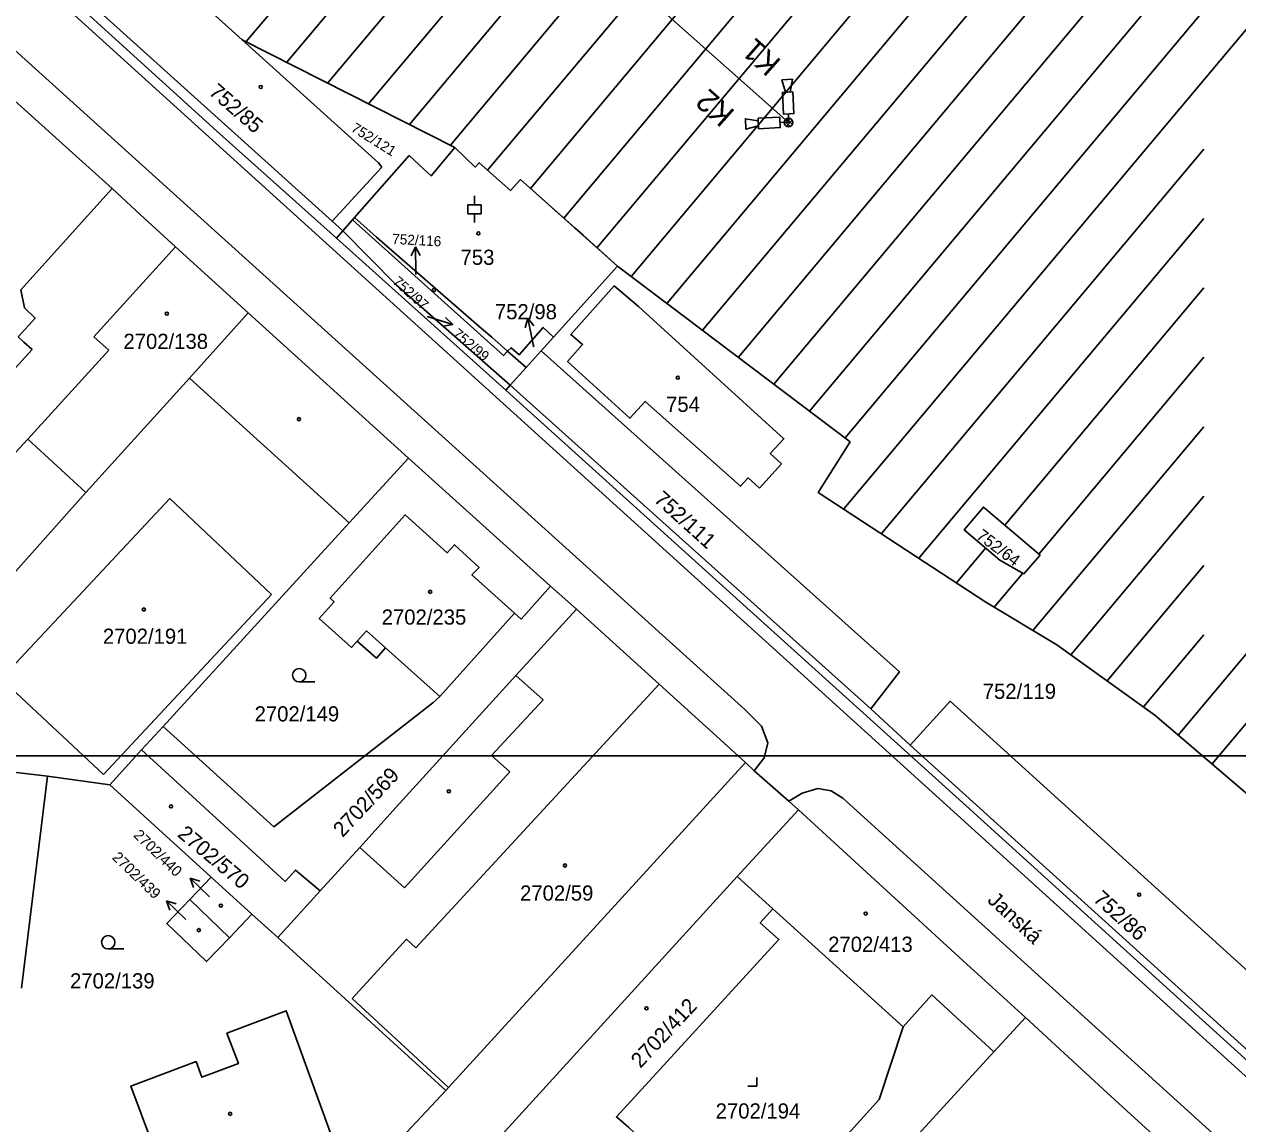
# Model space of a CAD drawing. Extents: x -496682 to -495776, y -1088797 to -1088018.
# Drawn here: x -496329.9 to -496193.9, y -1088502.5 to -1088379.3 of the extents above; entities that cross this region are included whole.
import ezdxf

# ---------------------------------------------------------------- set-up
doc = ezdxf.new("R2010")
doc.units = 0
for name, color, linetype in [('_PS01_CCTV', 7, 'Continuous'), ('Default', 7, 'Continuous'), ('Hranice parcel', 7, 'Continuous'), ('Parcelní čísla', 7, 'Continuous'), ('Pop  PČ popisy', 7, 'Continuous'), ('Vnitřní kresba', 7, 'Continuous'), ('Vrstva 20', 7, 'Continuous'), ('Vrstva 54', 7, 'Continuous'), ('Vrstva 63', 7, 'Continuous'), ('Značky budov', 7, 'Continuous'), ('Značky kultur', 7, 'Continuous')]:
    doc.layers.add(name, color=color, linetype=linetype)

# ---------------------------------------------------------------- blocks, each defined once
blk = doc.blocks.new('kamera na stožáru')
at = {"layer": 'Default'}
for p, q in [((-0.00047, -0.00014), (0.00014, 0.00046)), ((-0.00024, -0.00043), (0.00043, 0.00023)), ((0.00005, 0.00096), (0.00003, 0))]:
    blk.add_line(p, q, dxfattribs=at)
blk.add_lwpolyline([(0.00036, 0.00339), (0.00066, 0.00481), (-0.00052, 0.00481), (-0.00019, 0.0034)], dxfattribs=at)
blk.add_lwpolyline([(0.00065, 0.00339), (0.00064, 0.00096), (-0.00053, 0.00096), (-0.00053, 0.0034)], close=True, dxfattribs=at)
blk.add_circle((0, 0), 0.000488, dxfattribs=at)
blk.add_circle((0, 0), 0.000488, dxfattribs=at)
blk.add_circle((0, 0), 0.000488, dxfattribs=at)

msp = doc.modelspace()

# ---------------------------------------------------------------- linework, layer by layer
at = {"layer": '_PS01_CCTV'}
msp.add_line((-496244.22, -1088390.26), (-496278.91, -1088359.52), dxfattribs=at)
at = {"layer": 'Hranice parcel'}
for p, q in [((-496295.37, -1088401.32), (-496330.83, -1088369.38)), ((-496305.46, -1088381.01), (-496281.64, -1088393.07)), ((-496294.19, -1088402.41), (-496295.37, -1088401.32)), ((-496293.12, -1088401.19), (-496294.19, -1088402.41)), ((-496292.87, -1088400.91), (-496293.12, -1088401.19)), ((-496294.19, -1088402.41), (-496294.91, -1088403.24)), ((-496275.92, -1088420.27), (-496294.91, -1088403.24)), ((-496270.58, -1088414.34), (-496263.38, -1088406.35)), ((-496286.81, -1088427.89), (-496304.81, -1088411.58)), ((-496271.94, -1088415.85), (-496270.58, -1088414.34)), ((-496273.63, -1088417.73), (-496275.71, -1088415.91)), ((-496273.63, -1088417.73), (-496271.94, -1088415.85)), ((-496275.42, -1088419.72), (-496273.63, -1088417.73)), ((-496275.92, -1088420.27), (-496275.42, -1088419.72)), ((-496235.01, -1088455.98), (-496275.42, -1088419.72)), ((-496329.51, -1088425.77), (-496322.98, -1088431.74)), ((-496270.9, -1088442.22), (-496286.81, -1088427.89)), ((-496322.98, -1088431.74), (-496349.17, -1088461.01)), ((-496270.9, -1088442.22), (-496268.01, -1088444.81)), ((-496283.32, -1088454.6), (-496274.93, -1088445.27)), ((-496230.6, -1088460.05), (-496235.01, -1088455.98)), ((-496316.74, -1088460.58), (-496314.33, -1088457.95)), ((-496349.17, -1088461.01), (-496327.31, -1088463.52)), ((-496320.32, -1088464.49), (-496316.74, -1088460.58)), ((-496185.86, -1088500.52), (-496230.6, -1088460.05)), ((-496248.09, -1088462.93), (-496249.03, -1088461.98)), ((-496327.31, -1088463.52), (-496330.22, -1088487.27)), ((-496320.32, -1088464.49), (-496327.31, -1088463.52)), ((-496244.2, -1088466.33), (-496248.09, -1088462.93)), ((-496308.94, -1088474.84), (-496320.32, -1088464.49)), ((-496243.12, -1088467.31), (-496244.2, -1088466.33)), ((-496249.99, -1088474.77), (-496243.12, -1088467.31)), ((-496311.35, -1088477.35), (-496308.94, -1088474.84)), ((-496304.39, -1088478.97), (-496308.94, -1088474.84)), ((-496277.9, -1088505.38), (-496249.99, -1088474.77)), ((-496245.99, -1088478.39), (-496249.99, -1088474.77)), ((-496306.88, -1088481.63), (-496311.35, -1088477.35)), ((-496296.73, -1088476.39), (-496301.48, -1088481.61)), ((-496231.37, -1088491.6), (-496245.99, -1088478.39)), ((-496304.39, -1088478.97), (-496306.88, -1088481.63)), ((-496301.48, -1088481.61), (-496304.39, -1088478.97)), ((-496301.48, -1088481.61), (-496282.64, -1088498.73)), ((-496221.19, -1088494.41), (-496217.64, -1088490.55))]:
    msp.add_line(p, q, dxfattribs=at)
for points in [[(-496248.09, -1088462.93), (-496246.94, -1088461.48), (-496246.55, -1088459.79), (-496247.27, -1088457.92), (-496249.13, -1088456.06), (-496330.94, -1088382.16), (-496352.76, -1088362.17), (-496394.53, -1088322.76)], [(-496294.91, -1088403.24), (-496308.3, -1088391.23), (-496341.24, -1088361.35)], [(-496113.2, -1088569.45), (-496126.78, -1088557.15), (-496235.31, -1088458.83), (-496335.43, -1088368.13), (-496341.24, -1088361.35)], [(-496329.48, -1088364.15), (-496318.71, -1088373.85), (-496316.3, -1088371.21), (-496305.46, -1088381.01)], [(-496320.05, -1088397.68), (-496324.85, -1088393.33), (-496347.42, -1088372.97)], [(-496295.37, -1088401.32), (-496289.83, -1088395.26), (-496290.2, -1088394.8), (-496305.46, -1088381.01)], [(-496281.64, -1088393.07), (-496284.3, -1088396.25), (-496284.64, -1088395.96), (-496286.75, -1088393.98), (-496292.87, -1088400.91)], [(-496281.64, -1088393.07), (-496279.37, -1088395.26), (-496278.92, -1088394.77), (-496275.4, -1088397.89), (-496274.28, -1088396.67), (-496268.16, -1088402.12), (-496267.26, -1088402.88), (-496263.38, -1088406.35)], [(-496353.62, -1088434.72), (-496347.79, -1088428.16), (-496343.74, -1088431.85), (-496329.03, -1088415.71), (-496329.94, -1088414.89), (-496330.57, -1088414.27), (-496328.66, -1088412.18), (-496329.87, -1088411.04), (-496330.29, -1088409.02), (-496320.05, -1088397.68)], [(-496320.05, -1088397.68), (-496316.9, -1088400.57), (-496312.96, -1088404.2), (-496304.81, -1088411.58)], [(-496275.71, -1088415.91), (-496276.17, -1088416.39), (-496293.12, -1088401.19)], [(-496292.87, -1088400.91), (-496290.41, -1088403.13), (-496278.64, -1088413.37), (-496277.5, -1088414.34), (-496275.71, -1088415.91)], [(-496294.19, -1088402.41), (-496288.2, -1088408.47), (-496275.42, -1088419.72)], [(-496263.38, -1088406.35), (-496237.32, -1088426.06), (-496240.89, -1088431.73), (-496222.1, -1088444.04), (-496214.16, -1088448.81), (-496203.17, -1088456.69), (-496183.01, -1088473.86)], [(-496247.48, -1088431.25), (-496245.02, -1088428.51), (-496246.28, -1088427.38), (-496244.75, -1088425.7), (-496261.03, -1088410.9), (-496263.76, -1088408.58), (-496268.63, -1088414.01), (-496267.32, -1088415.15), (-496268.99, -1088417.07), (-496262.01, -1088423.42), (-496260.29, -1088421.52), (-496249.6, -1088431.03), (-496248.76, -1088430.1), (-496247.48, -1088431.25)], [(-496304.81, -1088411.58), (-496311.39, -1088418.91), (-496322.98, -1088431.74)], [(-496275.71, -1088415.91), (-496275.33, -1088415.51), (-496274.41, -1088416.29), (-496271.73, -1088413.23), (-496270.58, -1088414.34)], [(-496235.01, -1088455.98), (-496231.8, -1088451.84), (-496271.94, -1088415.85)], [(-496111.32, -1088569.45), (-496125.77, -1088556.38), (-496187.85, -1088499.89), (-496224.3, -1088466.84), (-496274.7, -1088421.37), (-496275.92, -1088420.27)], [(-496353.62, -1088434.72), (-496344.49, -1088436.33), (-496341.48, -1088433.73), (-496338.95, -1088435.92), (-496329.51, -1088425.77)], [(-496286.81, -1088427.89), (-496293.46, -1088435.15), (-496314.33, -1088457.95)], [(-496216.02, -1088438.77), (-496217.83, -1088440.84), (-496220.52, -1088439.31), (-496224.52, -1088435.92), (-496222.37, -1088433.36), (-496216.02, -1088438.77)], [(-496283.32, -1088454.6), (-496289.39, -1088449.15), (-496290.42, -1088450.31), (-496292.57, -1088448.38), (-496293.21, -1088449.09), (-496296.84, -1088445.84), (-496295.16, -1088443.98), (-496295.61, -1088443.57), (-496287.2, -1088434.24), (-496282.48, -1088438.48), (-496281.67, -1088437.59), (-496278.91, -1088440.14), (-496279.72, -1088440.96), (-496274.93, -1088445.27)], [(-496274.93, -1088445.27), (-496274.21, -1088445.91), (-496270.9, -1088442.22)], [(-496268.01, -1088444.81), (-496274.79, -1088452.23), (-496288.2, -1088467.01), (-496292.3, -1088471.51), (-496296.73, -1088476.39)], [(-496249.03, -1088461.98), (-496258.73, -1088453.21), (-496268.01, -1088444.81)], [(-496314.33, -1088457.95), (-496301.91, -1088469.21), (-496284.09, -1088455.32), (-496283.32, -1088454.6)], [(-496185.86, -1088500.52), (-496181.41, -1088495.65), (-496226.11, -1088455.1), (-496230.6, -1088460.05)], [(-496316.74, -1088460.58), (-496305.3, -1088471.05), (-496300.65, -1088475.31), (-496299.49, -1088474.04), (-496296.73, -1088476.39)], [(-496282.64, -1088498.73), (-496282.35, -1088498.41), (-496249.03, -1088461.98)], [(-496244.2, -1088466.33), (-496242.71, -1088465.41), (-496240.93, -1088464.91), (-496239.45, -1088465.16), (-496238.15, -1088465.99), (-496132.08, -1088562.07), (-496131.43, -1088562.99), (-496131.42, -1088564), (-496132.07, -1088565.26)], [(-496217.64, -1088490.55), (-496224.63, -1088484.22), (-496243.12, -1088467.31)], [(-496306.88, -1088481.63), (-496309.46, -1088484.31), (-496313.92, -1088480.03), (-496311.35, -1088477.35)], [(-496245.99, -1088478.39), (-496247.4, -1088479.95), (-496245.31, -1088481.83), (-496263.51, -1088501.71), (-496262.11, -1088502.91), (-496260.17, -1088504.72), (-496261.08, -1088505.74), (-496268.24, -1088513.68)], [(-496231.37, -1088491.6), (-496228.16, -1088488.03), (-496221.19, -1088494.41)], [(-496305.69, -1088507.24), (-496310.68, -1088509.11), (-496311.29, -1088507.46), (-496313.75, -1088508.38), (-496313.97, -1088507.79), (-496315.1, -1088504.6), (-496315.52, -1088504.76), (-496317.97, -1088498.28), (-496310.64, -1088495.51), (-496309.98, -1088497.27), (-496305.9, -1088495.73), (-496307.18, -1088492.33), (-496300.54, -1088489.82), (-496295.6, -1088503.41), (-496302.16, -1088505.89)], [(-496190.39, -1088515.55), (-496208.5, -1088499), (-496217.64, -1088490.55)], [(-496268.24, -1088513.68), (-496265.8, -1088515.77), (-496265.43, -1088515.37), (-496255.1, -1088526.07), (-496251.45, -1088521.81), (-496251.15, -1088518.66), (-496234.05, -1088499.76), (-496231.37, -1088491.6)], [(-496221.19, -1088494.41), (-496230.49, -1088504.55), (-496214.35, -1088519.32)], [(-496282.64, -1088498.73), (-496287, -1088503.42), (-496289.92, -1088506.42), (-496292.31, -1088508.31), (-496294.86, -1088509.98), (-496297.59, -1088511.42), (-496300.41, -1088512.61), (-496303.13, -1088513.62), (-496305.98, -1088514.4), (-496309.41, -1088514.94), (-496310.93, -1088514.97), (-496313.55, -1088515.26), (-496317.24, -1088515.06), (-496320.12, -1088514.76), (-496333.4, -1088513.15)]]:
    msp.add_lwpolyline(points, dxfattribs=at)
at = {"layer": 'Pop  PČ popisy'}
for p, q in [((-496286.05, -1088404.19), (-496286.54, -1088405.2)), ((-496286, -1088407.19), (-496286.05, -1088404.19)), ((-496286.05, -1088404.19), (-496285.53, -1088405.18)), ((-496285.99, -1088407.3), (-496286, -1088407.19)), ((-496284.72, -1088412.02), (-496281.85, -1088412.9)), ((-496281.85, -1088412.9), (-496282.66, -1088412.13)), ((-496273.46, -1088412.2), (-496273.75, -1088413.28)), ((-496272.84, -1088415.13), (-496273.46, -1088412.2)), ((-496273.46, -1088412.2), (-496272.77, -1088413.07)), ((-496281.85, -1088412.9), (-496282.95, -1088413.08)), ((-496272.78, -1088415.41), (-496272.84, -1088415.13)), ((-496309.14, -1088477.04), (-496311.3, -1088474.96)), ((-496311.3, -1088474.96), (-496310.23, -1088475.29)), ((-496311.3, -1088474.96), (-496310.93, -1088476.01)), ((-496311.79, -1088479.58), (-496313.95, -1088477.5)), ((-496313.95, -1088477.5), (-496312.88, -1088477.83)), ((-496313.95, -1088477.5), (-496313.58, -1088478.55))]:
    msp.add_line(p, q, dxfattribs=at)
at = {"layer": 'Vnitřní kresba'}
for p, q in [((-496312.96, -1088404.2), (-496322.1, -1088414.27)), ((-496322.1, -1088414.27), (-496320.41, -1088415.8)), ((-496320.41, -1088415.8), (-496329.51, -1088425.77)), ((-496293.46, -1088435.15), (-496311.39, -1088418.91)), ((-496332.48, -1088452.62), (-496313.58, -1088432.42)), ((-496313.58, -1088432.42), (-496302.2, -1088443.15)), ((-496302.2, -1088443.15), (-496321.03, -1088463.34)), ((-496291.53, -1088447.22), (-496292.57, -1088448.38)), ((-496289.39, -1088449.15), (-496291.53, -1088447.22)), ((-496321.03, -1088463.34), (-496332.48, -1088452.62)), ((-496271.73, -1088454.95), (-496274.79, -1088452.23)), ((-496285.99, -1088482.77), (-496258.73, -1088453.21)), ((-496277.51, -1088461.21), (-496271.73, -1088454.95)), ((-496275.48, -1088463.04), (-496277.51, -1088461.21)), ((-496287.29, -1088476.05), (-496275.48, -1088463.04)), ((-496292.3, -1088471.51), (-496287.29, -1088476.05)), ((-496293.16, -1088488.43), (-496287.06, -1088481.79)), ((-496287.06, -1088481.79), (-496285.99, -1088482.77)), ((-496282.35, -1088498.41), (-496293.16, -1088488.43))]:
    msp.add_line(p, q, dxfattribs=at)
at = {"layer": 'Vrstva 20'}
for p, q in [((-496282.13, -1088392.8), (-496217.45, -1088315.71)), ((-496277.96, -1088395.6), (-496209.98, -1088314.59)), ((-496273.15, -1088397.65), (-496205.29, -1088316.78)), ((-496269.42, -1088400.98), (-496201.55, -1088320.1)), ((-496265.66, -1088404.29), (-496197.81, -1088323.42)), ((-496261.83, -1088407.5), (-496194.07, -1088326.74)), ((-496257.84, -1088410.52), (-496190.33, -1088330.06)), ((-496253.85, -1088413.54), (-496186.59, -1088333.38)), ((-496305.04, -1088381.2), (-496266.65, -1088335.45)), ((-496249.85, -1088416.56), (-496182.85, -1088336.7)), ((-496300.46, -1088383.52), (-496262.89, -1088338.75)), ((-496245.86, -1088419.58), (-496179.11, -1088340.03)), ((-496295.88, -1088385.84), (-496259.13, -1088342.05)), ((-496241.87, -1088422.6), (-496175.37, -1088343.35)), ((-496291.3, -1088388.16), (-496255.38, -1088345.36)), ((-496237.88, -1088425.62), (-496171.63, -1088346.67)), ((-496286.72, -1088390.48), (-496251.62, -1088348.66)), ((-496238.03, -1088433.58), (-496167.89, -1088349.99)), ((-496233.82, -1088436.34), (-496197.66, -1088393.25)), ((-496229.61, -1088439.1), (-496197.66, -1088401.03)), ((-496219.97, -1088435.39), (-496197.66, -1088408.81)), ((-496216.16, -1088438.63), (-496197.66, -1088416.58)), ((-496216.82, -1088447.19), (-496197.66, -1088424.36)), ((-496212.58, -1088449.92), (-496197.66, -1088432.14)), ((-496225.4, -1088441.86), (-496222.11, -1088437.94)), ((-496221.16, -1088444.59), (-496217.94, -1088440.76)), ((-496208.5, -1088452.85), (-496197.66, -1088439.92)), ((-496204.43, -1088455.77), (-496197.66, -1088447.7)), ((-496200.54, -1088458.91), (-496191.43, -1088448.05)), ((-496196.73, -1088462.15), (-496184.9, -1088448.05))]:
    msp.add_line(p, q, dxfattribs=at)
at = {"layer": 'Vrstva 54'}
msp.add_lwpolyline([(-496237.32, -1088426.06), (-496263.38, -1088406.35), (-496274.28, -1088396.67), (-496275.4, -1088397.89), (-496278.92, -1088394.77), (-496279.37, -1088395.26), (-496281.64, -1088393.07), (-496305.46, -1088381.01), (-496316.3, -1088371.21)], dxfattribs=at)
at = {"layer": 'Vrstva 63'}
msp.add_lwpolyline([(-496137.35, -1088164.24), (-496137.35, -1088461.24), (-496557.35, -1088461.24), (-496557.35, -1088164.24)], close=True, dxfattribs=at)
at = {"layer": 'Značky budov'}
for centre in [(-496303.39, -1088386.28), (-496278.99, -1088402.7), (-496283.96, -1088409.03), (-496313.92, -1088411.69), (-496256.64, -1088418.87), (-496299.1, -1088423.51), (-496284.4, -1088442.87), (-496316.5, -1088444.85), (-496282.3, -1088465.22), (-496313.45, -1088466.91), (-496269.28, -1088473.54), (-496204.92, -1088476.81), (-496307.87, -1088478.03), (-496235.57, -1088478.92), (-496310.33, -1088480.78), (-496260.15, -1088489.55), (-496306.82, -1088501.37)]:
    msp.add_circle(centre, 0.175, dxfattribs=at)
at = {"layer": 'Značky kultur'}
for p, q in [((-496279.44, -1088399.49), (-496279.44, -1088398.49)), ((-496280.19, -1088399.49), (-496278.69, -1088399.49)), ((-496280.19, -1088400.49), (-496280.19, -1088399.49)), ((-496278.69, -1088400.49), (-496278.69, -1088399.49)), ((-496280.19, -1088400.49), (-496278.69, -1088400.49)), ((-496279.44, -1088401.49), (-496279.44, -1088400.49)), ((-496299.08, -1088452.96), (-496297.33, -1088452.96)), ((-496320.49, -1088482.89), (-496318.74, -1088482.89)), ((-496247.79, -1088498.28), (-496247.79, -1088497.28)), ((-496248.79, -1088498.28), (-496247.79, -1088498.28))]:
    msp.add_line(p, q, dxfattribs=at)
for centre in [(-496299.08, -1088452.21), (-496320.49, -1088482.14)]:
    msp.add_circle(centre, 0.75, dxfattribs=at)

# ---------------------------------------------------------------- block references
at = {"layer": '_PS01_CCTV'}
for xscale, yscale, rotation in [(1000, 999.9999999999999, 2.7497256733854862), (1000.0000000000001, 1000.0000000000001, 92.95538615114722)]:
    msp.add_blockref('kamera na stožáru', (-496244.22, -1088390.26), dxfattribs=dict(at, xscale=xscale, yscale=yscale, rotation=rotation))

# ---------------------------------------------------------------- texts
for s, p in [('K1', (-496244.92, -1088383.38)), ('K2', (-496250.11, -1088389.06))]:
    msp.add_text(s, height=2.5, rotation=138.43, dxfattribs=at).set_placement(p)
at = {"layer": 'Parcelní čísla'}
for s, height, rotation, p in [('752/85', 1.7, 319, (-496309.32, -1088387.03)), ('752/121', 1.139, 328, (-496293.35, -1088391.18)), ('752/116', 1.139, 357, (-496288.68, -1088403.87)), ('752/97', 1.139, 318, (-496288.68, -1088408.24)), ('752/99', 1.139, 320, (-496281.95, -1088414.12)), ('752/111', 1.7, 318, (-496259.43, -1088432.66)), ('752/64', 1.334, 323, (-496223.27, -1088436.8)), ('2702/569', 1.7, 47, (-496294.21, -1088470.46)), ('2702/570', 1.7, 320, (-496312.83, -1088470.2)), ('2702/440', 1.2, 316, (-496317.74, -1088470.23)), ('2702/439', 1.2, 316, (-496320.13, -1088472.73)), ('752/86', 1.7, 318, (-496210.18, -1088477.44)), ('2702/412', 1.7, 47, (-496260.82, -1088496.33))]:
    msp.add_text(s, height=height, rotation=rotation, dxfattribs=at).set_placement(p)
for s, p in [('753', (-496280.99, -1088406.22)), ('752/98', (-496277.14, -1088412.32)), ('2702/138', (-496318.78, -1088415.64)), ('754', (-496257.95, -1088422.7)), ('2702/235', (-496289.83, -1088446.54)), ('2702/191', (-496321.09, -1088448.69)), ('752/119', (-496222.45, -1088454.86)), ('2702/149', (-496304.08, -1088457.39)), ('2702/59', (-496274.32, -1088477.47)), ('2702/413', (-496239.78, -1088483.21)), ('2702/139', (-496324.77, -1088487.31)), ('2702/194', (-496252.39, -1088501.89))]:
    msp.add_text(s, height=1.7, dxfattribs=at).set_placement(p)
at = {"layer": 'Pop  PČ popisy'}
msp.add_text('Janská', height=1.7, rotation=317, dxfattribs=at).set_placement((-496222.03, -1088477.54))

doc.saveas('drawing.dxf')
